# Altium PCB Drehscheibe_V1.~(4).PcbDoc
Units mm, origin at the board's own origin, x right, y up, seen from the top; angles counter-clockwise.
Board outline 100 x 80 mm, 2 copper layers (Top Layer, Bottom Layer); 76 components, 66 nets, 323 pads, 1 vias.
Unrouted connection lines stored in the file: 175.
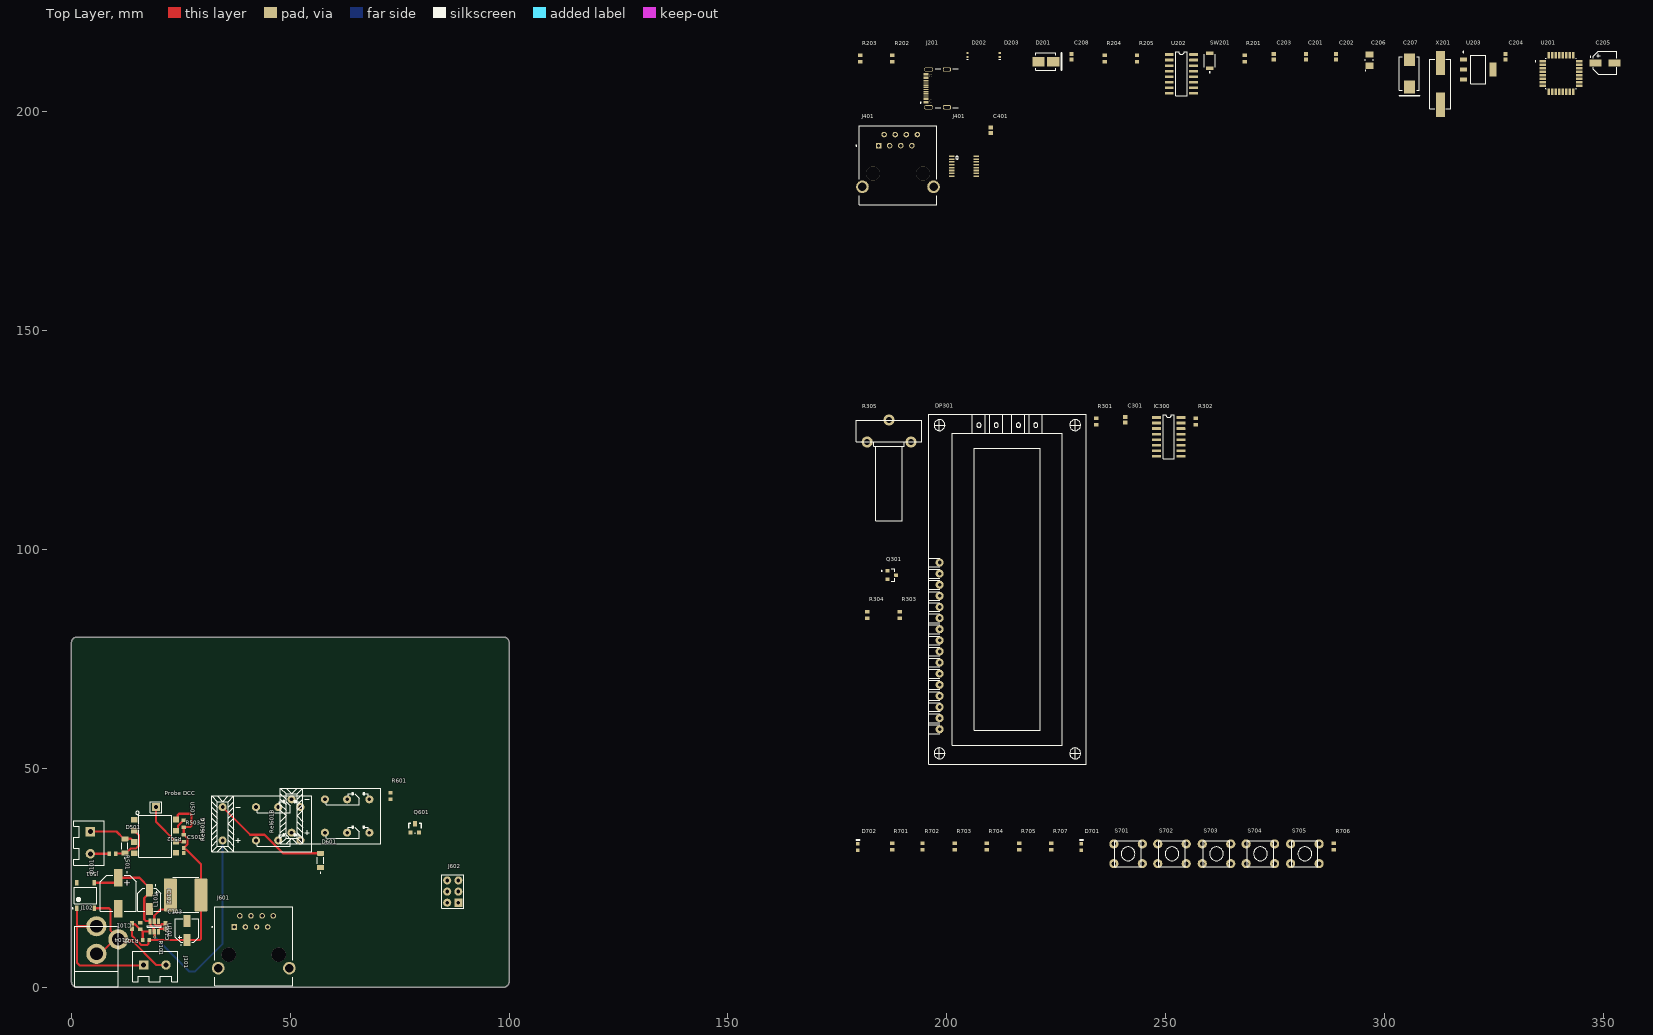
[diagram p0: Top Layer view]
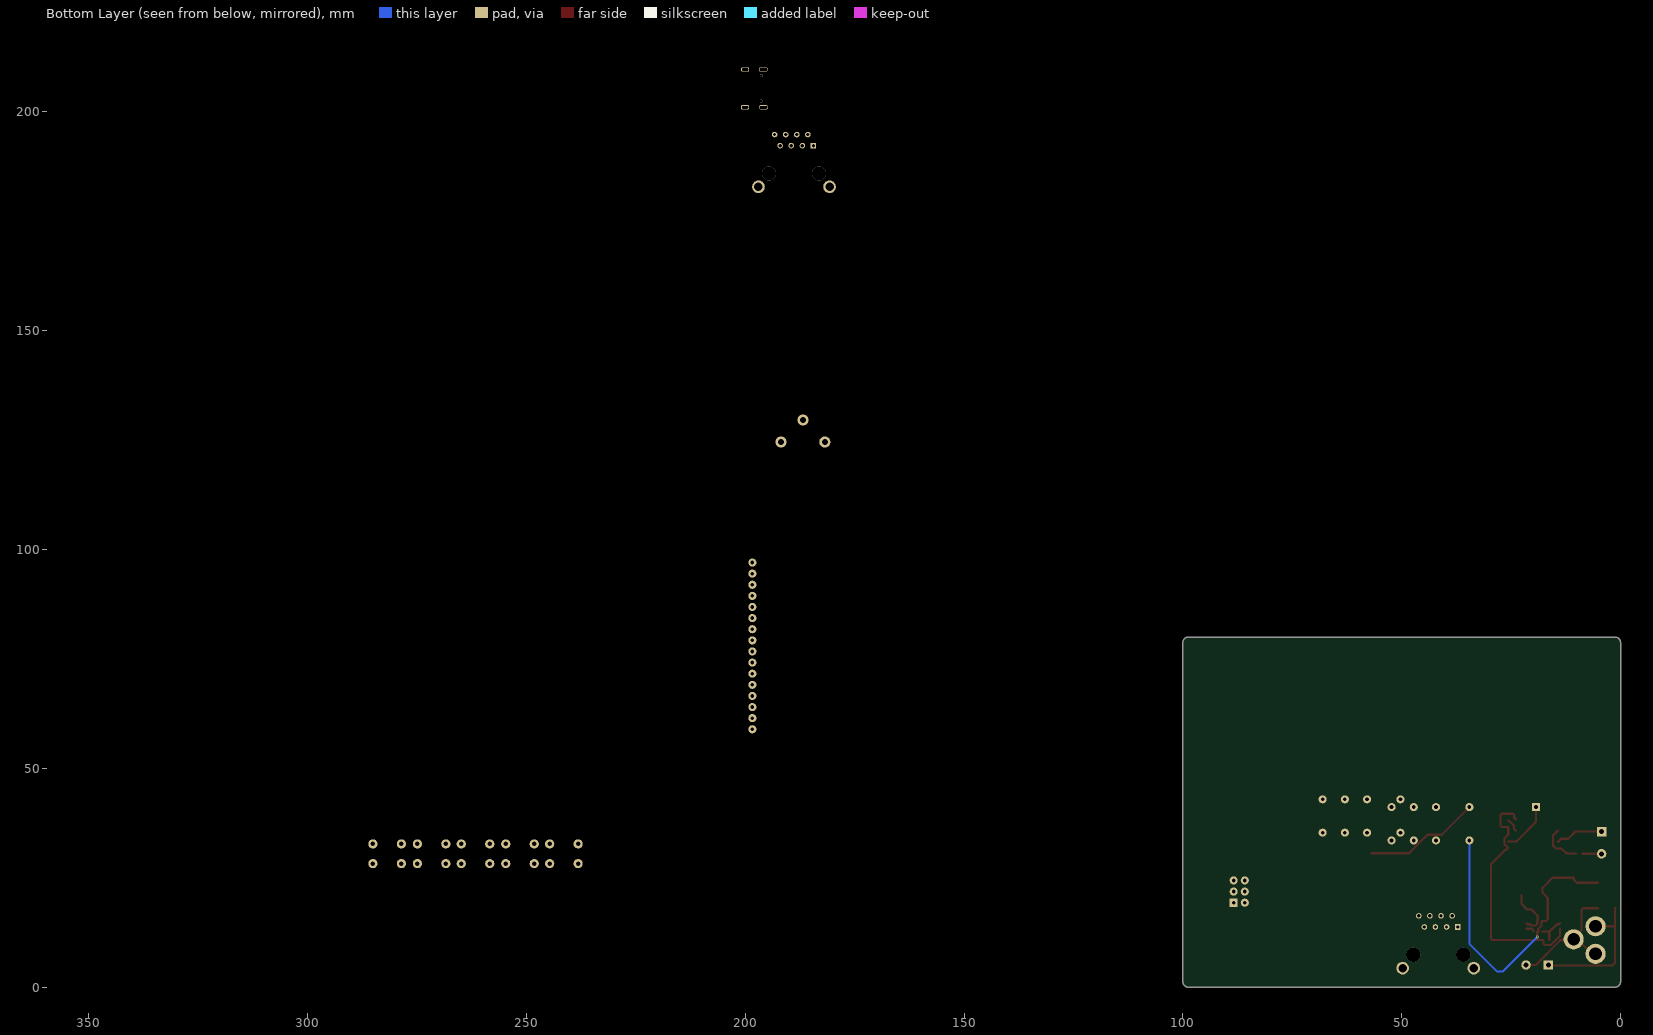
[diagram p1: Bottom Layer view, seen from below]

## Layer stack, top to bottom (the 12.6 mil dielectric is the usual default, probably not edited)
Top Solder: solder mask 0.0102, Solder Resist, Dk 3.5
Top Layer: signal copper 0.0356
Dielectric 1: dielectric 0.32, FR-4, Dk 4.8
Bottom Layer: signal copper 0.0356
Bottom Solder: solder mask 0.0102, Solder Resist, Dk 3.5

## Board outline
0,1.27 0,78.73 cw(c1.27,78.73) 1.27,80 98.73,80 cw(c98.73,78.73) 100,78.73 100,1.27 cw(c98.73,1.27) 98.73,0 1.27,0 cw(c1.27,1.27)

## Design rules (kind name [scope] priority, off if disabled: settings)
BoardOutlineClearance [All] p1: gap=0.2 ignorepadtopadclearanceinfootprint=FALSE
Clearance [All] p1: gap=0.127 ignorepadtopadclearanceinfootprint=FALSE except(0.25: Arc-Hole Track-Hole SMDPad-Hole THPad-Hole Via-Hole Fill-Hole Poly-Hole Region-Hole Text-Hole)
ComponentClearance [All] p1: gap=0.127 collisioncheckmode=3 verticalgap=0.127 showdistances=TRUE
DiffPairsRouting [All] p1: maxlimit=0.254 minlimit=0.127 mostfreqgap=0.127 toplayer_minwidth=0.127 toplayer_maxwidth=25.4 toplayer_prefwidth=0.127 bottomlayer_minwidth=0.127 bottomlayer_maxwidth=25.4 bottomlayer_prefwidth=0.127 maxuncoupledlength=12.7
Height [All] p1: minheight=0 maxheight=1816.048 prefheight=12.7
HoleSize [All] p1: absolutevalues=TRUE maxlimit=6.3 minlimit=0.3 maxpercent=80.000 minpercent=20.000
HoleToHoleClearance [All] p1: gap=0.25 allowstackedmicrovias=FALSE
MinimumAnnularRing [All] p1: minimumring=0.076
MinimumSolderMaskSliver [All] p1: minsoldermaskwidth=0
PlaneClearance [All] p1: clearance=0.127
PlaneConnect PlaneConnectPowerPads [InPadClass('PowerPads')] p1: planeconnectstyle=Direct reliefexpansion=0.508 reliefentries=4 reliefconductorwidth=0.254 reliefairgap=0.254
PlaneConnect [All] p2: pad.planeconnectstyle=Relief pad.reliefexpansion=0.3 pad.reliefentries=4 pad.reliefconductorwidth=0.127 pad.reliefairgap=0.127 via.planeconnectstyle=Direct via.reliefexpansion=0.3 via.reliefentries=4 via.reliefconductorwidth=0.127 via.reliefairgap=0.127
PolygonConnect PolygonConnectPowerPads [All vs (InPadClass('PowerPads'))] p1: connectstyle=Direct reliefconductorwidth=0.254 reliefentries=4 polygonreliefangle="90 Angle" airgapwidth=0.254
PolygonConnect [All] p2: thpad.connectstyle=Relief thpad.reliefconductorwidth=0.127 thpad.reliefentries=4 thpad.polygonreliefangle="90 Angle" thpad.airgapwidth=0.127 smdpad.connectstyle=Relief smdpad.reliefconductorwidth=0.127 smdpad.reliefentries=4 smdpad.polygonreliefangle="90 Angle" smdpad.airgapwidth=0.127 via.connectstyle=Direct via.reliefconductorwidth=0.127 via.reliefentries=4 via.polygonreliefangle="90 Angle" via.airgapwidth=0.127
RoutingVias [All] p1: holewidth=0.3 width=0.6 viastyle="Through Hole" minholewidth=0.3 minwidth=0.6 maxholewidth=0.6 maxwidth=6.6
SilkToSilkClearance [All] p1: silktosilkclearance=0
SilkToSolderMaskClearance [IsPad] p1: minsilkscreentomaskgap=0.127 clearancetoexposedcopper=TRUE
SolderMaskExpansion [All] p1: expansion=0.075 istentingtop=FALSE
Width [All] p1: maxlimit=25.4 minlimit=0.127 preferedwidth=0.127 minimp=50.000000 maximp=50.000000 favimp=50.000000
20 further rules are at their usual default settings.

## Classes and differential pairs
component class uC_V1: C201 C202 C203 C204 C205 C206 C207 C208 D201 D202 D203 J201 R201 R202 R203 R204 R205 SW201 U201 U202 U203 X201
component class Stepper_V1: C401 J401
component class "Relais und Connector_V1": D601 J601 J602 Q601 R601 Rel601A Rel601B Rel601C
component class PSU_V1: C101 C102 C103 C104 C105 D101 J101 J102 L101 R101 R102 U101
component class Display_V1: C301 DP301 IC300 Q301 R301 R302 R303 R304 R305
component class Demudulation_V1: C501 D501 J501 "Probe DCC" R501 R502 R503 U501
component class Bediehneinheit_V1: D701 D702 R701 R702 R703 R704 R705 R706 R707 S701 S702 S703 S704 S705

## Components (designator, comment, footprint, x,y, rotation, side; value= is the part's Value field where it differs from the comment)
C101 "470uf" C_SMD_F-TYP 10.7,21.45 r270 top
C102 "10uf" C_SMD_C-TYP 17.8,20 r270 top
C103 "Capacitor 100 nF +/-10% 50 V 0603" CAPC1608X90X40NL10T20 21.463,13.97 r90 top value=100nF
C104 "22pF" CAPC1608X90X40NL10T20 13.843,13.97 r270 top
C105 "22uf" C_SMD_C-TYP 26.416,12.954 r90 top
C201 "22pF" CAPC1608X90X40NL10T20 282.067,212.598 r90 top
C202 "22pF" CAPC1608X90X40NL10T20 288.925,212.598 r90 top
C203 "100nF" CAPC1608X90X40NL10T20 274.701,212.598 r90 top
C204 "100nF" CAPC1608X90X40NL10T20 327.66,212.598 r90 top
C205 "10uf" C_SMD_C-TYP 350.393,211.201 r0 top
C206 "TAJA106K016RNJ" CAPMP3217X18-T_V 296.545,211.836 r90 top value=10µF
C207 "293D226X9020D2TE3" VISH-7343-31_M 305.689,208.788 r90 top value=22µF
C208 "Capacitor 100 nF +/-10% 50 V 0603" CAPC1608X90X40NL10T20 228.473,212.598 r90 top value=100nF
C301 "100nF" CAPC1608X90X40NL10T20 240.792,129.667 r90 top
C401 "Capacitor 100 nF +/-10% 50 V 0603" CAPC1608X90X40NL10T20 210.058,195.834 r90 top value=100nF
C501 "Capacitor 1 uF +/- 10% 25 V 0603" CAPC1608X90X40LL10T20 25.654,31.242 r90 top value=1µF
D101 "*3D Model may have slightly different dimensions" SO-DIL-ABS-4mm 3.2,20.955 r90 top
D201 "SS54B" JCET-SMB-2_M 222.631,211.455 r0 top
D202 "QBLP595-IB" QTB-QBLP595_V 204.724,212.979 r90 top
D203 "QBLP595-IB" QTB-QBLP595_V 212.09,212.979 r90 top
D501 "FDLL4148" DIOMELF3414N 12.192,32.258 r90 top
D601 "FDLL4148" DIOMELF3414N 56.896,28.956 r90 top
D701 "19-217/Y5C-AM1N1VY/3T" EVRL-0603-2_V 230.759,32.004 r90 top
D702 "19-217/Y5C-AM1N1VY/3T" EVRL-0603-2_V 179.705,32.004 r90 top
DP301 "LC-Display" V_THT_WM-C1610M 213.868,90.932 r90 top
IC300 "PCF8574" SO-16 247.904,130.175 r0 top
J101 "VIN" "J_THT_Printklemme 2x" 19.05,5.08 r0 top
J102 "DC-Buchse" J_THT_CJ-25 5.715,0.127 r90 top
J201 "USB4105GFA120" GCT_USB4105GFA120 200.025,205.359 r90 top
J401 "ULN2003A" TSSOP-16-TI 203.962,187.579 r0 top
J401 "RJ45-8N-B" TE_RJ45-8N-B 188.849,185.928 r0 top
J501 "DCC" "J_THT_Printklemme 2x" 4.318,33.02 r270 top
J601 "RJ45-8N-B" TE_RJ45-8N-B 41.656,7.405 r0 top
J602 "CON 2x3" J_2x3 87.122,21.844 r90 top
L101 "6,8uH" L_SMD_NPIS42LS 29.106,21.082 r90 top
"Probe DCC" "#Wert" SIP-1 19.304,42.418 r90 top
Q301 "BC847B" TRANS_BC847B 187.436,94.173 r0 top
Q601 "BC848B" SOT-23 77.521,35.306 r0 top
R101 "40k2" RESC1608X55X25ML10T15 17.018,10.795 r0 top
R102 "7k68" RESC1608X55X25ML10T15 15.748,13.97 r270 top
R201 "10k" RESC1608X55X25ML10T15 268.097,212.217 r90 top
R202 "5k1" RESC1608X55X25ML10T15 187.579,212.217 r90 top
R203 "5k1" RESC1608X55X25ML10T15 180.213,212.217 r90 top
R204 "Resistor 1k +/-1% 0603 100 mW" RESC1608X55X25ML10T15 236.093,212.217 r90 top value=1k
R205 "Resistor 1k +/-1% 0603 100 mW" RESC1608X55X25ML10T15 243.459,212.217 r90 top value=1k
R301 "10k" RESC1608X55X25ML10T15 234.188,129.286 r90 top
R302 "10k" RESC1608X55X25ML10T15 256.921,129.286 r90 top
R303 "10k" RESC1608X55X25ML10T15 189.23,85.09 r90 top
R304 "Resistor 1k +/-1% 0603 100 mW" RESC1608X55X25ML10T15 181.864,85.09 r90 top value=1k
R305 "POT" PT15 186.817,124.587 r0 top value=1k
R501 "Resistor 1k +/-1% 0603 100 mW" RESC1608X55X25ML10T15 9.398,30.48 r0 top value=1k
R502 "Resistor 10k +/-1% 0603 100 mW" RESC1608X55X25ML10T15 25.654,37.338 r270 top value=10k
R503 "Resistor 10k +/-1% 0603 100 mW" RESC1608X55X25ML10T15 25.654,34.036 r90 top value=10k
R601 "Resistor 1k +/-1% 0603 100 mW" RESC1608X55X25ML10T15 72.898,43.688 r90 top value=1k
R701 "Resistor 10k +/-1% 0603 100 mW" RESC1608X55X25ML10T15 187.579,32.131 r90 top value=10k
R702 "Resistor 10k +/-1% 0603 100 mW" RESC1608X55X25ML10T15 194.437,32.131 r90 top value=10k
R703 "Resistor 10k +/-1% 0603 100 mW" RESC1608X55X25ML10T15 201.803,32.131 r90 top value=10k
R704 "Resistor 10k +/-1% 0603 100 mW" RESC1608X55X25ML10T15 209.169,32.131 r90 top value=10k
R705 "Resistor 10k +/-1% 0603 100 mW" RESC1608X55X25ML10T15 216.535,32.131 r90 top value=10k
R706 "470" RESC1608X55X25ML10T15 288.417,32.131 r90 top
R707 "470" RESC1608X55X25ML10T15 223.901,32.131 r90 top
Rel601A "Nais Relais" Rel_THT_Nais 43.434,37.338 r180 top
Rel601B "Nais Relais" Rel_THT_Nais 59.182,39.116 r180 top
Rel601C "Nais Relais" Rel_THT_Nais 43.434,37.338 r180 top
S701 "Taster4Kl." S_THT_Taster4kl. 241.427,30.48 r0 top
S702 "Taster4Kl." S_THT_Taster4kl. 251.46,30.48 r0 top
S703 "Taster4Kl." S_THT_Taster4kl. 261.62,30.48 r0 top
S704 "Taster4Kl." S_THT_Taster4kl. 271.653,30.48 r0 top
S705 "Taster4Kl." S_THT_Taster4kl. 281.813,30.48 r0 top
SW201 "B3U-1000P" OMRON-B3U-1000_V 260.096,211.709 r90 top
U101 "DIO6970" SOT23-6 19.873,12.7 r270 top
U201 "ATMEGA328P-AU" QFP80P900X900X120-32N 340.36,208.788 r0 top
U202 "CH340" SO-16 250.825,213.106 r0 top
U203 "#Wert" U_SMD_AMS1117 321.437,209.677 r0 top
U501 "6N137S" 8-SMD 19.304,34.29 r270 top
X201 "16MHz" X_SMD_XTAL 312.801,206.375 r90 top

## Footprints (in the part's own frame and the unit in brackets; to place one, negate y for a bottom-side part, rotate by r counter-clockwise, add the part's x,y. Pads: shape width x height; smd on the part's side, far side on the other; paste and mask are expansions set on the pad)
8-SMD [mm]
  rect 1.3x1.4 smd: 1(-3.96,-4.96) 2(-1.42,-4.96) 3(1.12,-4.96) 4(3.66,-4.96) 5(3.59,4.58) 6(1.05,4.58) 7(-1.49,4.58) 8(-4.03,4.58)
  silkscreen extent -5.92,-4.6 4.57,3.56, body extent -5.08,-4.84 5.08,4.84, height 4.6
C_SMD_C-TYP [mm] "LB-2024-04-15"
  rrect15% 2.8x1.6 smd paste-0.02 mask+0.05: 1(-2.15,0) 2(2.15,0)
  silkscreen extent -3.4,-2.65 2.65,2.65, body extent 0,0 0,0
C_SMD_F-TYP [mm] "LB-2024-04-16"
  rrect15% 4x2 smd paste-0.02 mask+0.05: 1(-3.55,0) 2(3.55,0)
  silkscreen extent -4.9,-4.15 4.15,4.15, body extent 0,0 0,0
CAPC1608X90X40LL10T20 [mm] "Chip Capacitor, 2-Leads, Body 1.70x0.90mm, IPC High Density"
  rect 0.85x0.85 smd: 1(-0.575,0) 2(0.575,0)
  body extent -0.85,-0.45 0.85,0.45, height 0.9
CAPC1608X90X40NL10T20 [mm] "Chip Capacitor, 2-Leads, Body 1.70x0.90mm, IPC Medium Density"
  rect 0.95x0.95 smd: 1(-0.625,0) 2(0.625,0)
  body extent -0.85,-0.45 0.85,0.45, height 0.9
CAPMP3217X18-T_V [mm] "Molded Capacitor, 2-Leads, Body 3.40x1.8mm"
  rect 1.4x1.8 smd: 1(-1.3,0) 2(1.3,0)
  silkscreen extent -2.45,-0.9 0.2,0.95, body extent -1.92,-0.9 1.92,0.9, height 1.8
DIOMELF3414N [mm]
  rrect25% 1.14x1.63 smd: A(1.64,0) C(-1.64,0)
  silkscreen extent -2.89,-0.7 0.75,0.7, body extent -1.7,-0.7 1.7,0.7, height 1.4
EVRL-0603-2_V [mm] "SMD, 2-Leads, Body 1.6x0.8mm"
  rect 0.8x0.8 smd: 1(-0.75,0) 2(0.75,0)
  silkscreen extent 1.65,-0.4 1.65,0.4, body extent -0.8,-0.4 0.8,0.4, height 0.5
GCT_USB4105GFA120 [mm]
  rect 0.6x1.15 smd: A1_B12(-3.2,4.755) A4_B9(-2.4,4.755) B1_A12(3.2,4.755) B4_A9(2.4,4.755)
  rect 0.3x1.15 smd: A5(-1.25,4.755) A6(-0.25,4.755) A7(0.25,4.755) A8(1.25,4.755) B5(1.75,4.755) B6(0.75,4.755) B7(-0.75,4.755) B8(-1.75,4.755)
  oval 1x2.1 hole 0.6 slot 1.7 at 90 deg: SH1(-4.32,4.18) SH2(4.32,4.18)
  rrect50% 1x1.8 hole 0.6 slot 1.4 at 90 deg: SH3(-4.32,0) SH4(4.32,0)
  round 0.65 hole 0.65 unplated: ""(-2.89,3.68) ""(2.89,3.68)
  silkscreen extent -4.47,-2.6 4.47,6.1, body extent -4.47,-2.6 4.47,5.11, height 3.31
J_2x3 [mm] "LB-2024-04-19"
  rect 1.85x1.85 hole 0.85 mask+0.102: 1(-2.54,-1.27)
  round 1.85 hole 0.85 mask+0.102: 2(-2.54,1.27) 3(0,-1.27) 4(0,1.27) 5(2.54,-1.27) 6(2.54,1.27)
  silkscreen extent -3.81,-2.54 3.81,2.54
J_THT_CJ-25 [mm] "LB-2024-04-19"
  round 4.6 hole 2.9: 1(13.8,0) 2(7.5,0) 3(10.8,-5)
  silkscreen extent 0,-5 13.8,5
"J_THT_Printklemme 2x" [mm] "LB-2024-04-17"
  rect 2.15x2.15 hole 1.15: 1(-2.54,0)
  round 2.15 hole 1.15: 2(2.54,0)
  silkscreen extent -5,-3.81 5.19,3.17
JCET-SMB-2_M [mm] "Molded Diode, 2-Leads, Body 4.57x3.94mm"
  rect 2.85x2.25 smd: 1(-1.675,0) 2(1.675,0)
  silkscreen extent -2.3,-2 3.6,2, body extent -2.5,-1.97 2.5,1.97, height 2.44
L_SMD_NPIS42LS [mm] "LB-2024-04-17"
  rrect15% 7.5x3 smd paste-0.02 mask+0.05: 1(0,-0.5) 2(0,6.5)
  silkscreen extent -4,0 4,6
OMRON-B3U-1000_V [mm] "SMD, 2-Leads, Body 3x2.5mm"
  rect 0.8x1.7 smd: 1(-1.7,0) 2(1.7,0)
  silkscreen extent -2.77,-1.25 1.5,1.25, body extent -1.5,-1.25 1.5,1.25, height 1.75
PT15 [mm]
  round 2.54 hole 1.35: 1(-5.006,-0.011) 2(4.994,-0.011) 3(-0.006,4.989)
  silkscreen extent -7.51,-18 7.49,4.99
QFP80P900X900X120-32N [mm]
  rrect25% 1.47x0.55 smd paste+0 mask+0.102: 1(-4.17,2.8) 2(-4.17,2) 3(-4.17,1.2) 4(-4.17,0.4) 5(-4.17,-0.4) 6(-4.17,-1.2) 7(-4.17,-2) 8(-4.17,-2.8) 17(4.17,-2.8) 18(4.17,-2) 19(4.17,-1.2) 20(4.17,-0.4) 21(4.17,0.4) 22(4.17,1.2) 23(4.17,2) 24(4.17,2.8)
  rrect25% 0.55x1.47 smd paste+0 mask+0.102: 9(-2.8,-4.17) 10(-2,-4.17) 11(-1.2,-4.17) 12(-0.4,-4.17) 13(0.4,-4.17) 14(1.2,-4.17) 15(2,-4.17) 16(2.8,-4.17) 25(2.8,4.17) 26(2,4.17) 27(1.2,4.17) 28(0.4,4.17) 29(-0.4,4.17) 30(-1.2,4.17) 31(-2,4.17) 32(-2.8,4.17)
  silkscreen extent -5.94,-3.5 3.5,3.5, body extent -4.5,-4.5 4.5,4.5, height 1.2
QTB-QBLP595_V [mm] "SMD, 2-Leads, Body 1x0.5mm"
  rrect25% 0.5x0.55 smd: 1(-0.455,0) 2(0.455,0)
  silkscreen extent -0.9,-0.2 -0.9,0.2, body extent -0.5,-0.25 0.5,0.25, height 0.5
Rel_THT_Nais [mm] "LB-2024-04-17"
  round 1.85 hole 0.85: 1(-8.89,-3.81) 2(-3.81,-3.81) 3(1.27,-3.81) 4(8.89,-3.81) 5(8.89,3.81) 6(1.27,3.81) 7(-3.81,3.81) 8(-8.89,3.81)
  silkscreen extent -11.43,-6.35 11.43,6.35
RESC1608X55X25ML10T15 [mm] "Chip Resistor, 2-Leads, Body 1.70x0.90mm, IPC Low Density"
  rect 0.8x1 smd: 1(-0.75,0) 2(0.75,0)
  body extent -0.85,-0.45 0.85,0.45, height 0.55
S_THT_Taster4kl. [mm] "LB-2024-04-17"
  round 2.1 hole 1.05: 1(-3.25,2.25) 1(3.25,2.25) 2(-3.25,-2.25) 2(3.25,-2.25)
  silkscreen extent -3,-3 3,3
SIP-1 [mm] "LB-2024-04-17"
  rect 1.85x1.85 hole 0.85: 1(-1.27,0)
  silkscreen extent -2.54,-1.27 0,1.27
SO-16 [mil] "LB-2024-04-17"
  rrect15% 80x24 smd paste-0.79 mask+1.97: 1(0,0) 2(0,-50) 3(0,-100) 4(0,-150) 5(0,-200) 6(0,-250) 7(0,-300) 8(0,-350) 9(220,-350) 10(220,-300) 11(220,-250) 12(220,-200) 13(220,-150) 14(220,-100) 15(220,-50) 16(220,0)
  silkscreen extent 60,-370 160,25
SO-DIL-ABS-4mm [mm]
  rrect25% 1.3x0.8 smd: 1(-2.9,2)
  rrect25% 1.25x0.8 smd: 2(-2.9,-2) 3(2.9,-2) 4(2.9,2)
  silkscreen extent -3.05,-2.6 1.9,3.07, body extent -3.1,-2.47 3.09,2.48, height 1.5
SOT23-6 [mm] "LB-2024-04-25"
  rrect15% 1.3x0.7 smd paste-0.02 mask+0.05: 1(-2.4,0) 2(-2.4,-0.95) 3(-2.4,-1.9) 4(0,-1.9) 5(0,-0.95) 6(0,0)
  silkscreen extent -1.35,-2.5 -1.05,0.6
SOT-23 [mil]
  rect 36x36 smd: 1(0,0) 2(75,0)
  rect 36x50 smd: 3(38,80)
  silkscreen extent -20,-5 95,85
TE_RJ45-8N-B [mm]
  rect 1.268x1.268 hole 0.76: 1(-4.445,6.35)
  round 1.268 hole 0.76: 2(-3.175,8.89) 3(-1.905,6.35) 4(-0.635,8.89) 5(0.635,6.35) 6(1.905,8.89) 7(3.175,6.35) 8(4.445,8.89)
  round 2.895 hole 1.93: 9(-8.125,-3.05) 10(8.125,-3.05)
  round 3.25 hole 3.25 unplated: ""(-5.715,0) ""(5.715,0)
  silkscreen extent -9.63,-7.11 8.89,10.92
TRANS_BC847B [mm]
  rrect25% 0.9x0.8 smd paste+0 mask+0.102: 1(-1,0.95) 2(-1,-0.95) 3(1,0)
  silkscreen extent -2.4,-1.45 0.65,1.45, body extent -1.3,-1.52 1.3,1.52, height 1.3
TSSOP-16-TI [mm]
  rect 1.2x0.35 smd paste+0 mask+0: 1(-2.808,2.275) 2(-2.808,1.625) 3(-2.808,0.975) 4(-2.808,0.325) 5(-2.808,-0.325) 6(-2.808,-0.975) 7(-2.808,-1.625) 8(-2.808,-2.275) 9(2.795,-2.275) 10(2.795,-1.625) 11(2.795,-0.975) 12(2.795,-0.325) 13(2.795,0.325) 14(2.795,0.975) 15(2.795,1.625) 16(2.795,2.275)
  silkscreen extent -1.95,1.63 -1.3,2.27, body extent -4.06,-9.59 4.06,9.59, height 5.33
U_SMD_AMS1117 [mm] "LB-2024-04-17"
  rrect15% 1.604x0.952 smd paste-0.02 mask+0.05: 1(-3.395,2.29) 2(-3.395,0) 3(-3.395,-2.29)
  rrect15% 1.604x3.262 smd paste-0.02 mask+0.05: 2(3.395,0)
  silkscreen extent -3.52,-3.25 1.75,4.12
V_THT_WM-C1610M [mm] "LB-2024-04-19"
  round 1.85 hole 0.85: 1(-32,15.5) 2(-29.46,15.5) 3(-26.92,15.5) 4(-24.38,15.5) 5(-21.84,15.5) 6(-19.3,15.5) 7(-16.76,15.5) 8(-14.22,15.5) 9(-11.68,15.5) 10(-9.14,15.5) 11(-6.6,15.5) 12(-4.06,15.5) 13(-1.52,15.5) 14(1.02,15.5) 15(3.56,15.5) 16(6.1,15.5)
  silkscreen extent -40.01,-17.96 39.99,18.04
VISH-7343-31_M [mm] "Molded Capacitor, 2-Leads, Body 7.6x4.6mm, IPC Low Density"
  rect 2.95x2.55 smd: 1(-3.125,0) 2(3.125,0)
  silkscreen extent -5.1,-2.3 3.8,2.3, body extent -4.02,-2.3 4.02,2.3, height 3.1
X_SMD_XTAL [mm] "LB-2024-04-17"
  rect 5.5x2 smd: 1(-4.75,0) 2(4.75,0)
  silkscreen extent -5.7,-2.4 5.7,2.4

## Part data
C101 C102 C105 C205: library part C_SMD_ELK, "SMD Elektrolytkondensator"
C103 C104 C201 C202 C203 C204 C208 C301 C401: library part CMP-001-00017-6, "Chip Capacitor, 100 nF, +/- 10%, 50 V, 0603 (1608 Metric)", Capacitor Type=Ceramic, Case/Package=0603, Max Operating Temperature=125°C, Min Operating Temperature=-55°C, Tolerance=10%, Voltage Rating=50V
C206: library part CMP-001-00041-7, "Standard Tantalum, 10 uF, +/- 10%, 16 V, -55 to 125 degC, 1206 (3216 Metric), RoHS, Tape and Reel", Capacitor Type=Tantalum, Case/Package=1206, Manufacturer=AVX, Max Operating Temperature=125°C, Min Operating Temperature=-55°C, Package Description="2-Pin Surface Mount Device, Body 3.2 x 1.65 mm", Package Quantity=1, Package Reference=CAPMP3217X18-T, Tolerance=10%, Voltage Rating=16V
C207: library part CMP-001-00021-7, "Solid Tantalum Chip Capacitor, 22 uF, +/- 10%, 20 V, -55 to 125 degC, 2917 (7343 Metric), RoHS, Tape and Reel", Capacitor Type=Tantalum, Case/Package=7343-31, Manufacturer="Vishay Semiconductor", Max Operating Temperature=125°C, Min Operating Temperature=-55°C, Package Description="2-Pin Surface Mount Device, Body 7.3 x 4.3 mm", Tolerance=10%, Voltage Rating=20V
C501: library part CMP-001-00005-6, "Chip Capacitor, 1 uF, +/- 10%, 25 V, 0603 (1608 Metric)", Capacitor Type=Ceramic, Case/Package=0603, Max Operating Temperature=125°C, Min Operating Temperature=-55°C, Tolerance=10%, Voltage Rating=25V
D101: library part Bridge_1ph
D201: library part CMP-004-00006-2, "Schottky Barrier Rectifier, 40 V, 5 A, -55 to 150 degC, 2-Pin SMD", Case/Package=SMB-2, Manufacturer=JCET, Package Description="2-Pin Surface Mount Device, Body 4.315 x 3.62 mm"
D202 D203: library part CMP-007-00042-3, "Chip LED 0402, Blue, 0.02 A, 3.1 to 3.7 V, -40 to 80 degC, 2-Pin SMD, RoHS, Tape and Reel", Case/Package=0402, Colour=Blue
D501 D601: "Diode Standard 100 V 200mA Surface Mount SOD-80", Package="SOD-80-2 ON Semiconductor"
D701 D702: library part CMP-007-00005-2, "Chip LED, Yellow, 5 V, 25mA, -40 to 85 degC, 2-Pin SMD (0603), RoHS, Tape and Reel", Case/Package=0603, Manufacturer="Everlight Electronics", Package Description="2-Pin Surface Mount Device, Body 1.6 x 0.8 mm"
DP301: library part "V_THT_LCD Modul", "LCD"
IC300: library part IC_PCF8574, "I/O Expander"
J101 J501: library part "J_THT_Printklemme 2x", "Printklemme"
J102: library part J_THT_Hohlstecker
J201: "USB CONN, 2.0 TYPE C, RCPT, 16POS, SMT; USB Connector Type:USB Type C; USB Standard:USB 2.0; Gender:Receptacle; No. of Positions:16Positions; Connector Mounting:Surface Mount, Through Hole Mount; Orientation:Right Angle RoHS Compliant: Yes", Package=None
J401: "DARLINGTON ARRAY 7NPN, 2003, DIP16; Transistor Polarity:NPN; Collector Emitter Voltage V(br)ceo:50V; DC Collector Current:500mA; DC Current Gain hFE:1000; Operating Temperature Range:-20Â°C to +85Â°C; Transistor Case Style:DIP; No. of Pins:16; SVHC:No SVH", Package="DIP-16 Sprague"
J401 J601: "RJ Jack / Signal Line EMI/RFI Filters 6 TERM LOW PROFILE BLOCK INDUCTOR 8 PIN", Package=None
J602: library part "J_THT_IDC 2x3", "Stecker"
L101: library part L_SMD_Spule, "Spule SMD"
"Probe DCC": library part J_THT_CON1, "Stecker"
Q301: "BJT, SOT-23, 45V, 100mA, NPN, 0.25W, 150Â°C", Package="SOT-23 Diotec"
Q601: library part Q_SMD_NPN, "NPN Transistor"
R101 R102 R201 R202 R203 R301 R302 R303 R502 R503 R701 R702 R703 R704 R705 R706 R707: library part CMP-009-00017-5, "Chip Resistor, 10 KOhm, +/- 1%, 01 W, -55 to 155 degC, 0603 (1608 Metric)", Case/Package=0603, Max Operating Temperature=155°C, Min Operating Temperature=-55°C, Power=100mW, Tolerance=1%, Voltage Rating=50V
R204 R205 R304 R501 R601: library part CMP-009-00014-5, "Chip Resistor, 1 KOhm, +/-1%, 0.1 W, -55 to 155 degC, 0603 (1608 Metric)", Case/Package=0603, Max Operating Temperature=155°C, Min Operating Temperature=-55°C, Power=100mW, Tolerance=1%, Voltage Rating=50V
R305: "Potentiometer"
Rel601A Rel601B Rel601C: library part Rel_THT_Nais, "Nais DS2Y-S-DC12V"
S701 S702 S703 S704 S705: library part S_THT_Taster, "Taster"
SW201: library part CMP-011-00000-2, "Tactile Switch, SPST-NO, 0.05 A, 12 V, -25 to 70 degC, 2-Pin SMD, RoHS, Tape and Reel", Case/Package=B3U-1000, Contact Current Rating=50mA, IP Rating=IP40, Manufacturer="Omron Electronic Components", Max Contact Resistance=100mohm, Max Operating Temperature=70°C, Max Voltage Rating (DC)=12V, Min Operating Temperature=-25°C, Operating Force=153gf, Package Description="2-Pin Surface Mount Device, Body 3 x 2.5 mm", Package Quantity=3500, Resistance=0.1Ohm
U101: library part U_DIO6970, "Buckconverter"
U201: "MICROCONTROLLER MCU, 8 BIT, ATMEGA, 20MH; MICROCONTROLLER MCU, 8 BIT, ATMEGA, 20MHZ, TQFP-32; Controller Family/Series:ATmega; CPU Speed:20MHz; Program Memory Size:32KB; RAM Memory Size:2KB; No. of Pins:32Pins; MCU Case Style:TQFP; No. of I/O's:23I/O's; P", Package=None
U202: library part IC_CH340, "UART"
U203: library part U_SMD_AMS1117, "Linearwandler", Dropout Voltage=1.1V, Manufacturer="Advanced Monolithic Systems", Manufacturer Part Number=AMS1117-3.3, Max Junction Temp=+125°C, Max Power Dissipation=1.2W, Max Supply Voltage=15V, Nominal Supply Current=5mA, Output Current=1A, Output Voltage=3.3V, Package=AMS1117, Temperature="-40°C to +125°C", Temperature Range Low=-40°C
U501: "Logic Output Optoisolator 15MBd Open Collector 5000Vrms 1 Channel 10kV/µs CMTI 8-SMD", Package="SMD-8 Lite-On Inc."
X201: library part X_SMD_Quarz, "Quarz SMD"

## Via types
v1: diameter 0.6, hole 0.3, Top Layer to Bottom Layer, 1 vias

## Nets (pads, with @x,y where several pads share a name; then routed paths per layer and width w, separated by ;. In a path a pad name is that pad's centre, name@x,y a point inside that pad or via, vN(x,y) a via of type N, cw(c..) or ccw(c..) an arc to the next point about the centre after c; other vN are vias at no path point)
+3V3: C207.1 C208.2 R204.2 R205.2 U202.4 U202.16 U203.2
+5V: C104.2 C105.1 C204.2 C205.1 C206.1 C301.2 C401.2 C501.2 DP301.2 DP301.15 IC300.1 IC300.2 IC300.3 IC300.16 J401.9@206.757,185.304 J602.3 L101.1 R101.2 R201.1 R301.1 R302.1 R303.1 R305.2 R502.2 R503.2 R706.2 S701.2 S702.2 S703.2 S704.2 S705.2 U201.4 U201.6 U201.18 U203.3 U501.8 | length 56.2
  Top Layer w0.5: C104.2 13.843,11.787 15.978,9.652 17.325,9.652 17.618,9.945 17.618,10.645 R101.2 26.407,10.795 C105.1 29.313,10.804 29.606,11.097 L101.1 29.606,28.098 26.235,31.469 26.002,31.469 C501.2 26.531,32.694 26.531,34.009 25.754,34.786 R503.2 R502.2 27.139,36.588 27.432,36.881 27.432,39.331 27.139,39.624 24.576,39.624 24.284,39.331 24.284,38.72 U501.8
ADC6: U201.19
ADC7: U201.22
BL: IC300.7 R303.2 R304.1
D4: DP301.11 IC300.9
D5: DP301.12 IC300.10
D6: DP301.13 IC300.11
D7: DP301.14 IC300.12
D+: J201.A6 J201.B6 U202.5
D-: J201.A7 J201.B7 U202.6
DCC: "Probe DCC.1" R503.1 U201.2 U501.6 | length 11.6
  Top Layer w0.5: 19.304,41.148 19.304,37.77 23.834,33.24 U501.6 23.907,33.263 25.631,33.263 R503.1
EN: DP301.6 IC300.6
ESS: J401.8@193.294,194.818 J601.8 U201.10
FRST: R705.2 S705.1 U201.32
GND: C101.2 C102.2 C105.2 C201.1 C202.1 C203.1 C204.1 C205.2 C206.2 C207.2 C208.1 C301.1 C401.1 C501.1 D101.4 D702.2 DP301.1 DP301.5 IC300.5 IC300.8 J201.A1_B12 J201.B1_A12 J201.SH1 J201.SH2 J201.SH3 J201.SH4 J401.1@184.404,192.278 J401.8@201.154,185.304 J601.1 J602.1 Q301.2 Q601.2 R102.1 R202.2 R203.1 R305.1 R701.1 R702.1 R703.1 R704.1 R705.1 SW201.1 U101.1 U201.3 U201.5 U201.21 U202.1 U203.1 U501.5
GND-Diff: J401.2@185.674,194.818 J601.2 Rel601B.3
LED: D701.2 R707.2 U201.1
M1: J401.4@188.214,194.818 J401.16 J601.4
M2: J401.5@189.484,192.278 J401.15 J601.5
M3: J401.6@190.754,194.818 J401.14 J601.6
M4: J401.7@192.024,192.278 J401.13 J601.7
MISO: U201.16
MOSI: U201.15
NetC103_1: C103.1 U101.6 | length 2
  Top Layer w0.5: U101.6 19.873,13 20.218,13.345 C103.1
NetC103_2: C103.2 L101.2 U101.2 | length 11.6
  Top Layer w0.5: C103.2 21.238,14.37 20.645,14.37 20.348,14.073 19.398,14.073 19.023,14.448 19.023,15 U101.2 18.923,16.31 20.356,17.743 21.356,17.743 22.606,18.993 L101.2
NetC104_1: C104.1 R101.1 R102.2 U101.4 | length 7.2
  Top Layer w0.5: C104.1 14.068,14.37 14.498,14.37 15.648,13.22 R102.2 15.987,12.981 16.268,12.7 R101.1 ; R102.2@15.998,12.993 16.291,12.7 U101.4
NetC201_2: C201.2 U201.7 X201.1
NetC202_2: C202.2 U201.8 X201.2
NetC203_2: C203.2 U201.20
NetD201_1: D201.1 J201.A4_B9 J201.B4_A9
NetD202_2: D202.2 R204.1
NetD203_2: D203.2 R205.1
NetD501_A: D501.A J501.1 U501.3 | length 11
  Top Layer w0.5: J501.1 10.285,35.56 11.947,33.898 D501.A 13.601,33.898 13.894,33.605 13.894,33.57 14.294,33.17 U501.3
NetD501_C: D501.C R501.2 U501.2 | length 9.9
  Top Layer w0.5: R501.2 10.217,30.549 12.123,30.549 D501.C 12.437,30.618 13.476,31.657 14.714,31.657 15.421,32.364 15.421,34.683 14.394,35.71 U501.2
NetD601_A: D601.A Q601.3 Rel601A.4 | length 26.7
  Top Layer w0.5: Rel601A.4 40.862,34.83 44.101,34.83 48.335,30.596 D601.A
NetD701_1: D701.1 R706.1
NetD702_1: D702.1 R707.1
NetDP301_3: DP301.3 R305.3
NetDP301_16: DP301.16 Q301.3
NetJ201_A5: J201.A5 R202.1
NetJ201_B5: J201.B5 R203.2
NetJ501_2: J501.2 R501.1 | length 4.3
  Top Layer w0.5: J501.2 R501.1
NetQ301_1: Q301.1 R304.2
NetQ601_1: Q601.1 R601.2
NetR502_1: R502.1 U501.7 | length 3.1
  Top Layer w0.5: U501.7 23.934,35.78 24.334,36.18 24.334,36.868 25.554,38.088 R502.1
RS: DP301.4 IC300.4
RST: R201.2 SW201.2 U201.29
RX: D203.1 U201.30 U202.2
SCK: U201.17
SCL: IC300.14 R301.2 U201.28
SDA: IC300.15 R302.2 U201.27
SM1: J401.1@201.154,189.854 U201.12
SM2: J401.2@201.154,189.204 U201.13
SM3: J401.3@201.154,188.554 U201.14
SM4: J401.4@201.154,187.904 U201.11
T-180: J602.4 R703.2 S703.1 U201.25
T-+: J602.5 R701.2 S701.1 U201.23
T--: J602.2 R702.2 S702.1 U201.24
T-Play: J602.6 R704.2 S704.1 U201.26
TX: D202.1 U201.31 U202.3
VCC: C101.1 C102.1 D101.3 D201.2 D601.C Rel601A.5 U101.3 U101.5 | length 72.3
  Top Layer w0.5: D101.3 9.95,23.855 10.7,24.605 C101.1 15.55,25 17.8,22.75 17.8,21.55 16.623,20.373 16.623,15.503 17.026,15.1 U101.3 18.073,15 18.073,14.102 18.823,13.352 18.823,12.8 U101.5 19.023,12.6 19.023,11.526 19.05,11.499 v1(19.05,11.472)
  Bottom Layer w0.5: v1(19.05,11.472) 26.966,3.556 28.194,3.556 34.544,9.906 Rel601A.5@34.544,33.242
VCC-Diff: J401.3@186.944,192.278 J601.3 Rel601C.6
VSSW: R601.1 U201.9
VW1: D101.2 J101.2 J102.2 J102.3 Rel601B.2 Rel601C.8 | length 31.1
  Top Layer w0.5: D101.2 8.597,18.055 8.89,17.762 8.89,13.001 10.715,11.176 J102.3 ; J102.2 6.565,7.627 9.865,10.927 J102.3 ; J101.2 19.407,5.08 13.765,10.722 10.92,10.722 J102.3
VW2: D101.1 J101.1 J102.1 Rel601B.1 Rel601C.7 | length 32.6
  Top Layer w0.5: D101.1 1.27,17.985 1.27,14.15 ; J102.1 1.493,13.927 1.27,14.15 ; J101.1 16.38,4.95 1.908,4.95 1.27,5.588 1.27,14.15
pads on no net: DP301.7 DP301.8 DP301.9 DP301.10 IC300.13 J201. J201.A8 J201.B8 J401. J401.5@201.154,187.254 J401.6@201.154,186.604 J401.7@201.154,185.954 J401.9@180.724,182.878 J401.10 J401.11 J401.12 J601. J601.9 J601.10 Rel601A.1 Rel601A.2 Rel601A.3 Rel601A.6 Rel601A.7 Rel601A.8 Rel601B.4 Rel601B.5 Rel601B.6 Rel601B.7 Rel601B.8 Rel601C.1 Rel601C.2 Rel601C.3 Rel601C.4 Rel601C.5 U202.7 U202.8 U202.9 U202.10 U202.11 U202.12 U202.13 U202.14 U202.15 U501.1 U501.4

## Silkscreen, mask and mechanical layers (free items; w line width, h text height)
Board Shape:
  lines w0.254: 0,1.27 ccw(c1.27,1.27) 1.27,0 98.73,0 ccw(c98.73,1.27) 100,1.27 100,78.73 ccw(c98.73,78.73) 98.73,80 1.27,80 ccw(c1.27,78.73) 0,78.73 0,2 0,1.27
